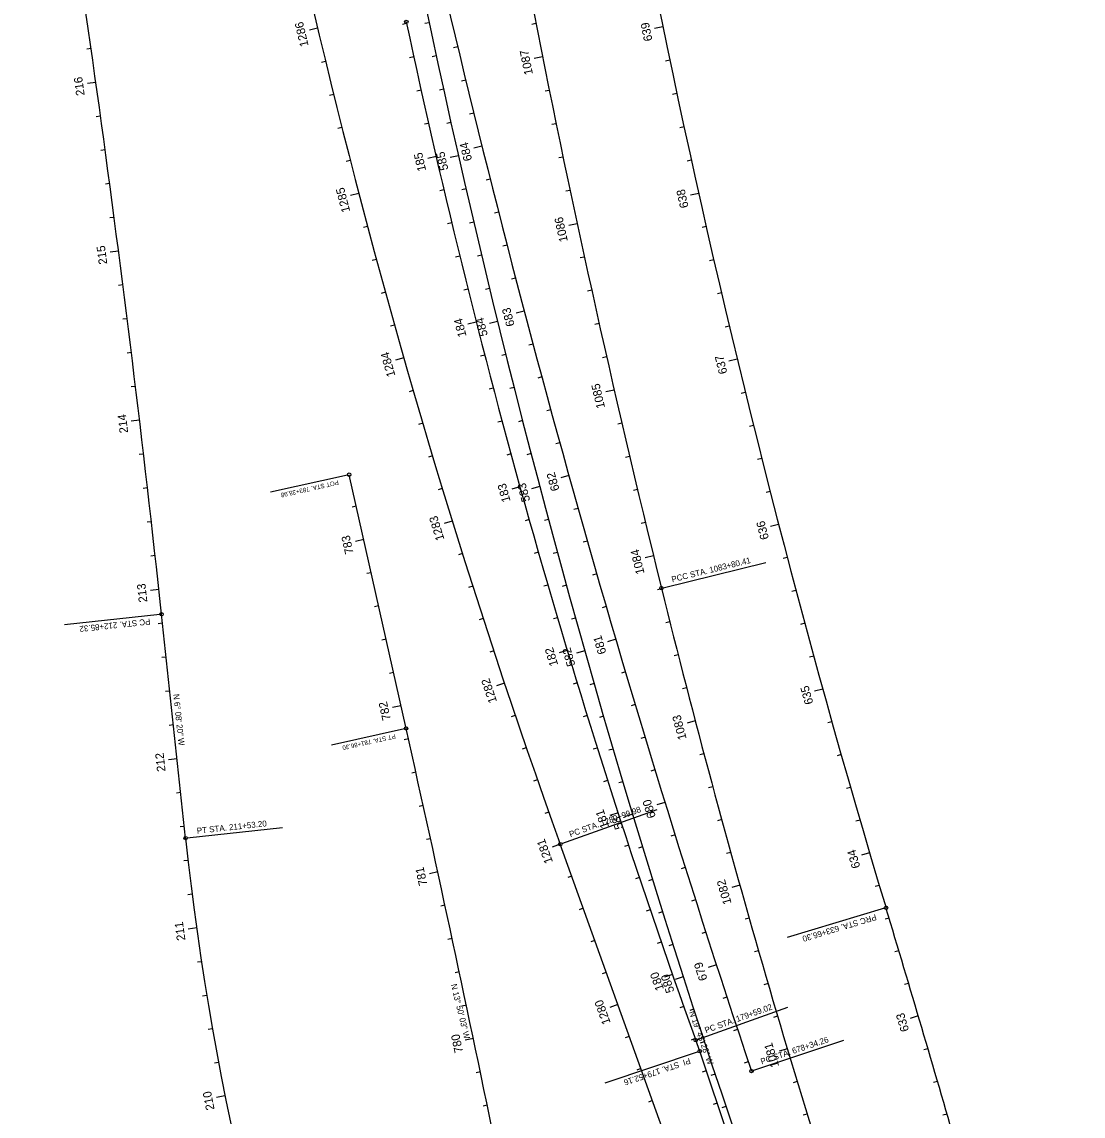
# Model space of a CAD drawing. Extents: x 919452 to 931278, y 583254 to 665650.
# Drawn here: x 928872 to 929495, y 633795 to 634438 of the extents above; entities that cross this region are included whole.
import ezdxf

# ---------------------------------------------------------------- set-up
doc = ezdxf.new("R2010")
doc.units = 0
for name, color, linetype in [('CLConst_dp', 7, 'Continuous'), ('CurveDataLabel_dp', 7, 'Continuous'), ('StationTicL_dp', 7, 'Continuous'), ('StationTicS_dp', 7, 'Continuous'), ('TextBLStation', 7, 'Continuous'), ('TextLabel', 7, 'Continuous')]:
    doc.layers.add(name, color=color, linetype=linetype)

msp = doc.modelspace()

# ---------------------------------------------------------------- linework, layer by layer
at = {"layer": 'CLConst_dp'}
for p, q in [((929097.18, 634023.04), (929063.76, 634172.02)), ((928967.74, 633958.7), (928953.61, 634090.06)), ((929494.71, 633100.38), (929187.7, 633955.08)), ((929269.59, 633833.59), (929267.27, 633840.04)), ((929461.08, 633264.99), (929269.59, 633833.59))]:
    msp.add_line(p, q, dxfattribs=at)
for centre, radius, start, end in [((934714.76, 635630.15), 5729.58, 175.955434, 198.89818), ((935122.08, 635647.98), 5998.08, 187.109635, 196.766064), ((933402.41, 635468.98), 4478.35, 187.81416, 199.75791), ((936244.12, 635835), 7207.6, 188.199151, 193.884708), ((919061.67, 633026.13), 9949, 6.138854, 9.590734), ((936128.21, 636105.39), 7200, 192.636554, 198.491034), ((933581.09, 635389.53), 4583.66, 191.98316, 199.75791), ((934799.58, 635477.92), 5719.58, 193.88471, 198.61214), ((915974, 631079.31), 13449.29, 10.454203, 12.643022), ((930687.21, 634143.64), 1729.38, 186.13885, 201.15388), ((916462.13, 630026.27), 13490.3, 16.142538, 16.766064)]:
    msp.add_arc(centre, radius, start, end, dxfattribs=at)
at = {"layer": 'CurveDataLabel_dp'}
for p, q in [((929062.78, 634171.8), (929017.59, 634161.67)), ((929248.09, 634105.64), (929308.42, 634120.55)), ((928952.62, 634089.95), (928896.6, 634083.93)), ((929096.2, 634022.82), (929053.39, 634013.22)), ((929188.64, 633955.42), (929244.61, 633975.53)), ((928968.74, 633958.81), (929024.58, 633964.82)), ((929378.01, 633917.45), (929320.85, 633900.23)), ((929268.22, 633840.38), (929321.24, 633859.43)), ((929300.87, 633822.18), (929354.24, 633840.03)), ((929268.64, 633833.27), (929213.95, 633814.85))]:
    msp.add_line(p, q, dxfattribs=at)
for centre in [(929097.32, 634437.85), (929063.76, 634172.02), (929247.12, 634105.4), (928953.61, 634090.06), (929097.18, 634023.04), (928967.74, 633958.7), (929187.7, 633955.08), (929378.97, 633917.74), (929267.27, 633840.04), (929269.59, 633833.59), (929299.93, 633821.86)]:
    msp.add_circle(centre, 1, dxfattribs=at)
at = {"layer": 'StationTicL_dp'}
for p, q in [((929045.26, 634434.12), (929040.4, 634432.97)), ((929247.94, 634434.93), (929243.04, 634433.92)), ((929177.33, 634417.25), (929172.43, 634416.27)), ((928915.02, 634402.35), (928910.07, 634401.66)), ((929141.75, 634364.89), (929136.9, 634363.68)), ((929114.83, 634358.78), (929109.96, 634357.65)), ((929127.91, 634359.26), (929123.03, 634358.15)), ((929069.46, 634337.09), (929064.62, 634335.83)), ((929268.98, 634337.17), (929264.1, 634336.08)), ((929197.68, 634319.34), (929192.79, 634318.29)), ((928928.36, 634303.25), (928923.4, 634302.6)), ((929166.6, 634268.03), (929161.76, 634266.75)), ((929138.38, 634261.59), (929133.53, 634260.36)), ((929150.94, 634261.95), (929146.08, 634260.76)), ((929095.81, 634240.63), (929091, 634239.26)), ((929291.64, 634239.77), (929286.78, 634238.6)), ((929219.39, 634221.73), (929214.51, 634220.61)), ((928940.69, 634204.01), (928935.73, 634203.42)), ((929192.79, 634171.52), (929187.97, 634170.18)), ((929164.04, 634164.94), (929159.23, 634163.61)), ((929175.66, 634165.06), (929170.83, 634163.78)), ((929124.31, 634144.78), (929119.53, 634143.3)), ((929315.93, 634142.77), (929311.09, 634141.51)), ((929072.29, 634133.98), (929067.41, 634132.89)), ((929242.45, 634124.42), (929237.59, 634123.24)), ((928952.03, 634104.66), (928947.06, 634104.11)), ((929220.31, 634075.38), (929215.52, 634073.97)), ((929191.81, 634068.88), (929187.02, 634067.44)), ((929202.07, 634068.61), (929197.26, 634067.25)), ((929154.94, 634049.59), (929150.2, 634048.01)), ((929341.83, 634046.18), (929337.01, 634044.85)), ((929094.18, 634036.41), (929089.3, 634035.31)), ((929266.97, 634027.48), (929262.13, 634026.21)), ((928962.74, 634005.23), (928957.77, 634004.7)), ((929249.17, 633979.64), (929244.4, 633978.16)), ((929221.66, 633973.44), (929216.91, 633971.89)), ((929230.17, 633972.64), (929225.38, 633971.19)), ((929187.69, 633955.11), (929182.99, 633953.42)), ((929369.34, 633950.04), (929364.54, 633948.62)), ((929115.8, 633938.77), (929110.91, 633937.71)), ((929293.17, 633930.97), (929288.36, 633929.62)), ((928974.24, 633905.9), (928969.29, 633905.21)), ((929279.36, 633884.3), (929274.6, 633882.76)), ((929253.59, 633878.67), (929248.87, 633877.03)), ((929259.93, 633877.17), (929255.17, 633875.64)), ((929221.5, 633860.99), (929216.79, 633859.3)), ((929397.94, 633854.22), (929393.14, 633852.8)), ((929136.69, 633840.98), (929131.8, 633839.95)), ((929321.06, 633834.94), (929316.27, 633833.5)), ((928990.85, 633807.3), (928985.94, 633806.33))]:
    msp.add_line(p, q, dxfattribs=at)
at = {"layer": 'StationTicS_dp'}
for p, q in [((929097.52, 634436.88), (929095.08, 634436.36)), ((929110.71, 634437.39), (929108.26, 634436.87)), ((929173.43, 634436.86), (929170.97, 634436.38)), ((928912.23, 634422.16), (928909.76, 634421.81)), ((929127.49, 634423.17), (929125.06, 634422.59)), ((929049.93, 634414.67), (929047.5, 634414.09)), ((929101.72, 634417.33), (929099.28, 634416.8)), ((929114.9, 634417.83), (929112.46, 634417.3)), ((929252.02, 634415.35), (929249.57, 634414.84)), ((929132.19, 634403.73), (929129.76, 634403.14)), ((929054.68, 634395.25), (929052.25, 634394.65)), ((929106.01, 634397.79), (929103.57, 634397.25)), ((929119.17, 634398.29), (929116.73, 634397.76)), ((929181.29, 634397.65), (929178.84, 634397.15)), ((929256.16, 634395.78), (929253.71, 634395.26)), ((928917.77, 634382.54), (928915.29, 634382.2)), ((929136.94, 634384.3), (929134.51, 634383.71)), ((929059.52, 634375.84), (929057.09, 634375.23)), ((929110.38, 634378.27), (929107.94, 634377.72)), ((929123.5, 634378.77), (929121.06, 634378.22)), ((929185.31, 634378.05), (929182.86, 634377.55)), ((929260.37, 634376.23), (929257.92, 634375.7)), ((928920.47, 634362.73), (928918, 634362.39)), ((929064.44, 634356.46), (929062.02, 634355.84)), ((929189.38, 634358.47), (929186.93, 634357.96)), ((929264.64, 634356.69), (929262.2, 634356.15)), ((928923.14, 634342.9), (928920.66, 634342.57)), ((929146.61, 634345.49), (929144.19, 634344.88)), ((929119.37, 634339.3), (929116.94, 634338.73)), ((929132.38, 634339.77), (929129.94, 634339.2)), ((929193.5, 634338.9), (929191.06, 634338.38)), ((928925.77, 634323.08), (928923.29, 634322.75)), ((929151.53, 634326.1), (929149.1, 634325.49)), ((929074.55, 634317.76), (929072.14, 634317.11)), ((929124, 634319.84), (929121.57, 634319.26)), ((929136.91, 634320.29), (929134.48, 634319.72)), ((929273.38, 634317.66), (929270.94, 634317.1)), ((929156.5, 634306.73), (929154.08, 634306.11)), ((929079.74, 634298.44), (929077.33, 634297.79)), ((929128.71, 634300.4), (929126.28, 634299.81)), ((929141.52, 634300.83), (929139.09, 634300.25)), ((929201.91, 634299.8), (929199.47, 634299.26)), ((929277.85, 634298.16), (929275.41, 634297.6)), ((929161.52, 634287.37), (929159.1, 634286.74)), ((928930.9, 634283.41), (928928.42, 634283.09)), ((929085.01, 634279.15), (929082.6, 634278.48)), ((929133.5, 634280.99), (929131.08, 634280.38)), ((929146.19, 634281.38), (929143.76, 634280.79)), ((929206.2, 634280.26), (929203.76, 634279.72)), ((929282.38, 634278.69), (929279.95, 634278.11)), ((928933.41, 634263.57), (928930.93, 634263.26)), ((929090.37, 634259.88), (929087.96, 634259.2)), ((929210.54, 634260.74), (929208.1, 634260.19)), ((929286.98, 634259.22), (929284.55, 634258.64)), ((929171.73, 634248.7), (929169.31, 634248.05)), ((928935.88, 634243.72), (928933.4, 634243.41)), ((929143.34, 634242.22), (929140.92, 634241.59)), ((929155.75, 634242.54), (929153.32, 634241.93)), ((929214.94, 634241.23), (929212.5, 634240.67)), ((929176.91, 634229.38), (929174.5, 634228.73)), ((928938.31, 634223.87), (928935.82, 634223.57)), ((929101.34, 634221.41), (929098.94, 634220.71)), ((929148.39, 634222.86), (929145.97, 634222.23)), ((929160.62, 634223.14), (929158.2, 634222.53)), ((929296.37, 634220.34), (929293.94, 634219.74)), ((929182.15, 634210.08), (929179.74, 634209.42)), ((929106.95, 634202.22), (929104.55, 634201.51)), ((929153.53, 634203.53), (929151.11, 634202.89)), ((929165.57, 634203.76), (929163.15, 634203.14)), ((929223.89, 634202.24), (929221.46, 634201.68)), ((929301.16, 634200.92), (929298.74, 634200.32)), ((929187.44, 634190.79), (929185.03, 634190.13)), ((928943.04, 634184.15), (928940.56, 634183.86)), ((929112.65, 634183.04), (929110.26, 634182.33)), ((929158.74, 634184.23), (929156.33, 634183.57)), ((929170.58, 634184.4), (929168.16, 634183.77)), ((929228.45, 634182.77), (929226.02, 634182.19)), ((929306.02, 634181.52), (929303.6, 634180.91)), ((928945.35, 634164.28), (928942.87, 634164)), ((929118.44, 634163.9), (929116.05, 634163.17)), ((929233.06, 634163.31), (929230.63, 634162.73)), ((929310.94, 634162.14), (929308.52, 634161.52)), ((929067.91, 634153.5), (929065.48, 634152.95)), ((929198.18, 634152.26), (929195.78, 634151.58)), ((928947.62, 634144.41), (928945.13, 634144.13)), ((929169.43, 634145.68), (929167.02, 634145)), ((929180.81, 634145.73), (929178.4, 634145.08)), ((929237.73, 634143.86), (929235.3, 634143.27)), ((929203.64, 634133.02), (929201.23, 634132.33)), ((928949.85, 634124.54), (928947.36, 634124.26)), ((929130.26, 634125.69), (929127.88, 634124.94)), ((929174.9, 634126.44), (929172.49, 634125.75)), ((929186.03, 634126.42), (929183.61, 634125.77)), ((929320.98, 634123.42), (929318.56, 634122.78)), ((929076.67, 634114.47), (929074.23, 634113.92)), ((929209.14, 634113.79), (929206.74, 634113.1)), ((929136.31, 634106.62), (929133.93, 634105.86)), ((929180.45, 634107.23), (929178.05, 634106.53)), ((929191.31, 634107.13), (929188.9, 634106.47)), ((929247.22, 634105), (929244.79, 634104.4)), ((929326.1, 634104.08), (929323.68, 634103.44)), ((929081.05, 634094.95), (929078.61, 634094.41)), ((929214.7, 634094.58), (929212.3, 634093.88)), ((929142.43, 634087.58), (929140.06, 634086.81)), ((929186.09, 634088.04), (929183.69, 634087.33)), ((929196.66, 634087.86), (929194.25, 634087.19)), ((929252.05, 634085.59), (929249.63, 634084.99)), ((928954.18, 634084.77), (928951.7, 634084.5)), ((929331.28, 634084.76), (929328.86, 634084.11)), ((929085.42, 634075.44), (929082.99, 634074.89)), ((929148.64, 634068.57), (929146.27, 634067.79)), ((929256.96, 634066.2), (929254.53, 634065.59)), ((928956.32, 634064.89), (928953.84, 634064.62)), ((929336.52, 634065.46), (929334.11, 634064.8)), ((929089.8, 634055.92), (929087.36, 634055.38)), ((929225.98, 634056.2), (929223.58, 634055.49)), ((929197.61, 634049.74), (929195.22, 634049.01)), ((929207.56, 634049.38), (929205.16, 634048.69)), ((929261.93, 634046.83), (929259.51, 634046.21)), ((928958.46, 634045), (928955.97, 634044.73)), ((929231.7, 634037.04), (929229.3, 634036.32)), ((929161.32, 634030.64), (929158.96, 634029.83)), ((929203.5, 634030.62), (929201.11, 634029.88)), ((929213.11, 634030.16), (929210.71, 634029.46)), ((928960.6, 634025.12), (928958.11, 634024.85)), ((929347.2, 634026.92), (929344.8, 634026.24)), ((929098.56, 634016.89), (929096.12, 634016.35)), ((929237.47, 634017.89), (929235.08, 634017.16)), ((929167.79, 634011.71), (929165.42, 634010.9)), ((929209.47, 634011.53), (929207.09, 634010.78)), ((929218.73, 634010.97), (929216.33, 634010.26)), ((929272.07, 634008.14), (929269.65, 634007.5)), ((929352.64, 634007.67), (929350.24, 634006.99)), ((929102.91, 633997.37), (929100.47, 633996.83)), ((929243.3, 633998.76), (929240.9, 633998.02)), ((929174.34, 633992.81), (929171.98, 633991.99)), ((929215.53, 633992.47), (929213.14, 633991.71)), ((929224.41, 633991.79), (929222.02, 633991.08)), ((928964.88, 633985.35), (928962.39, 633985.08)), ((929277.24, 633988.82), (929274.83, 633988.17)), ((929358.14, 633988.44), (929355.74, 633987.75)), ((929107.23, 633977.84), (929104.79, 633977.31)), ((929180.97, 633973.95), (929178.62, 633973.11)), ((928967.02, 633965.46), (928964.53, 633965.19)), ((929282.49, 633969.52), (929280.07, 633968.86)), ((929363.71, 633969.23), (929361.31, 633968.53)), ((929111.53, 633958.31), (929109.09, 633957.78)), ((929255.1, 633960.54), (929252.72, 633959.79)), ((929227.88, 633954.43), (929225.51, 633953.65)), ((929235.99, 633953.5), (929233.6, 633952.77)), ((928969.2, 633945.58), (928966.72, 633945.29)), ((929287.79, 633950.24), (929285.38, 633949.57)), ((929261.09, 633941.45), (929258.7, 633940.7)), ((929194.45, 633936.29), (929192.1, 633935.44)), ((929234.19, 633935.45), (929231.82, 633934.66)), ((929241.87, 633934.39), (929239.48, 633933.65)), ((928971.61, 633925.73), (928969.13, 633925.41)), ((929375.03, 633930.87), (929372.64, 633930.15)), ((929120.03, 633919.23), (929117.59, 633918.7)), ((929267.13, 633922.39), (929264.74, 633921.63)), ((929201.21, 633917.46), (929198.86, 633916.62)), ((929240.57, 633916.5), (929238.21, 633915.69)), ((929247.83, 633915.29), (929245.44, 633914.55)), ((929298.61, 633911.73), (929296.21, 633911.04)), ((929380.78, 633911.71), (929378.39, 633910.99)), ((929124.24, 633899.67), (929121.8, 633899.15)), ((929273.22, 633903.34), (929270.84, 633902.57)), ((929207.97, 633898.64), (929205.62, 633897.79)), ((929247.04, 633897.57), (929244.68, 633896.76)), ((929253.84, 633896.22), (929251.46, 633895.46)), ((929304.12, 633892.5), (929301.72, 633891.81)), ((929386.53, 633892.56), (929384.14, 633891.84)), ((928977.11, 633886.11), (928974.64, 633885.73)), ((929128.42, 633880.12), (929125.98, 633879.59)), ((929214.74, 633879.82), (929212.38, 633878.97)), ((929309.7, 633873.29), (929307.3, 633872.59)), ((929392.25, 633873.39), (929389.85, 633872.68)), ((928980.2, 633866.35), (928977.73, 633865.95)), ((929132.57, 633860.55), (929130.13, 633860.03)), ((929285.56, 633865.29), (929283.18, 633864.51)), ((929260.23, 633859.81), (929257.87, 633858.97)), ((929266.08, 633858.14), (929263.71, 633857.37)), ((929315.34, 633854.11), (929312.95, 633853.4)), ((928983.52, 633846.62), (928981.06, 633846.2)), ((929228.26, 633842.17), (929225.9, 633841.33)), ((929291.81, 633846.29), (929289.43, 633845.51)), ((929266.94, 633840.97), (929264.59, 633840.12)), ((929272.3, 633839.13), (929269.93, 633838.35)), ((929403.6, 633835.04), (929401.2, 633834.33)), ((928987.07, 633826.94), (928984.61, 633826.48)), ((929235.02, 633823.35), (929232.67, 633822.5)), ((929273.47, 633822.07), (929271.1, 633821.27)), ((929298.11, 633827.31), (929295.74, 633826.52)), ((929140.79, 633821.4), (929138.34, 633820.89)), ((929278.59, 633820.14), (929276.21, 633819.35)), ((929326.83, 633815.79), (929324.44, 633815.07)), ((929409.23, 633815.84), (929406.83, 633815.14)), ((929241.78, 633804.53), (929239.43, 633803.68)), ((929279.86, 633803.11), (929277.49, 633802.31)), ((929144.85, 633801.82), (929142.4, 633801.31)), ((929284.94, 633801.18), (929282.57, 633800.38)), ((929332.68, 633796.67), (929330.29, 633795.93)), ((929414.83, 633796.65), (929412.43, 633795.95))]:
    msp.add_line(p, q, dxfattribs=at)

# ---------------------------------------------------------------- texts
at = {"layer": 'CurveDataLabel_dp'}
for s, height, rotation, p in [('POT STA. 783+38.98', 2.625, 192.64302, (929057.31, 634168.78)), ('PCC STA. 1083+80.41', 3.5, 13.88471, (929253.5, 634108.78)), ('PC STA. 212+85.32', 3.5, 186.13885, (928946.84, 634087.57)), ('PT STA. 781+86.30', 2.625, 192.64302, (929090.73, 634019.8)), ('PC STA. 1280+99.98', 3.5, 19.75791, (929193.7, 633959.1)), ('PT STA. 211+53.20', 3.5, 6.13885, (928974.52, 633961.19)), ('PRC STA. 633+66.30', 3.5, 196.76606, (929372.77, 633914.05)), ('PC STA. 179+59.02', 3.5, 19.75791, (929273.27, 633844.06)), ('PC STA. 678+34.26', 3.5, 18.49103, (929306.01, 633825.74)), ('PI  STA. 179+52.16', 3.5, 198.61187, (929263.52, 633829.7))]:
    msp.add_text(s, height=height, rotation=rotation, dxfattribs=at).set_placement(p)
at = {"layer": 'TextBLStation'}
for s, rotation, p in [('1286', 103.36063, (929040, 634423.85)), ('639', 101.66794, (929241.91, 634427.01)), ('1087', 101.34417, (929171.69, 634407.23)), ('216', 97.95109, (928908.5, 634394.84)), ('585', 102.81552, (929122.05, 634351.19)), ('684', 103.98902, (929136.04, 634356.78)), ('185', 102.9956, (929109, 634350.69)), ('1285', 104.64002, (929064.43, 634326.67)), ('638', 102.62318, (929263.09, 634329.12)), ('1086', 102.1391, (929192.2, 634309.18)), ('215', 97.37519, (928921.76, 634295.77)), ('683', 104.78479, (929161.03, 634259.74)), ('184', 104.2456, (929132.71, 634253.46)), ('584', 103.81552, (929145.2, 634253.86)), ('1284', 105.91941, (929090.99, 634230.18)), ('637', 103.57841, (929285.87, 634231.72)), ('1085', 102.93404, (929214.05, 634211.46)), ('214', 96.7993, (928934.01, 634196.68)), ('682', 105.58057, (929187.33, 634163.16)), ('183', 105.4956, (929158.58, 634156.59)), ('583', 104.81552, (929170.1, 634156.77)), ('1283', 107.19881, (929119.76, 634134.12)), ('636', 104.53365, (929310.31, 634134.56)), ('783', 102.64302, (929066.42, 634125.91)), ('1084', 103.72898, (929237.23, 634114.16)), ('213', 96.2234, (928945.29, 634097.29)), ('681', 106.37634, (929214.85, 634067.38)), ('182', 106.7456, (929186.52, 634060.41)), ('582', 105.81552, (929196.65, 634060.23)), ('1282', 108.4782, (929150.63, 634038.84)), ('635', 105.48888, (929336.36, 634037.85)), ('782', 102.64302, (929088.3, 634028.34)), ('1083', 104.69021, (929261.95, 634017.03)), ('212', 96.13885, (928955.99, 633997.88)), ('680', 107.17212, (929243.93, 633971.19)), ('181', 107.9956, (929216.43, 633965.29)), ('581', 106.81552, (929224.76, 633964.59)), ('1281', 109.7576, (929183.47, 633944.69)), ('634', 106.44411, (929363.98, 633941.7)), ('781', 102.27537, (929109.77, 633931.18)), ('1082', 105.69196, (929288.34, 633920.44)), ('211', 97.90155, (928967.66, 633898.79)), ('180', 109.2456, (929248.66, 633870.04)), ('679', 107.96789, (929274.24, 633875.78)), ('580', 107.81551, (929254.79, 633868.66)), ('1280', 109.75791, (929217.4, 633850.21)), ('633', 106.48449, (929392.62, 633845.77)), ('780', 101.84936, (929130.69, 633833.06)), ('1081', 106.6937, (929316.28, 633824.76)), ('210', 101.21464, (928984.76, 633799.44))]:
    msp.add_text(s, height=5, rotation=rotation, dxfattribs=at).set_placement(p)
at = {"layer": 'TextLabel'}
for s, rotation, p in [('N 6%%d 08\' 20" W', 276.13885, (928960.43, 634043.09)), ('N 13%%d 50\' 03" W', 283.8342, (929123.46, 633872.61)), ('N 19%%d 45\' 28" W', 289.75791, (929263.25, 633856.41))]:
    msp.add_text(s, height=3.5, rotation=rotation, dxfattribs=at).set_placement(p)

doc.saveas('drawing.dxf')
